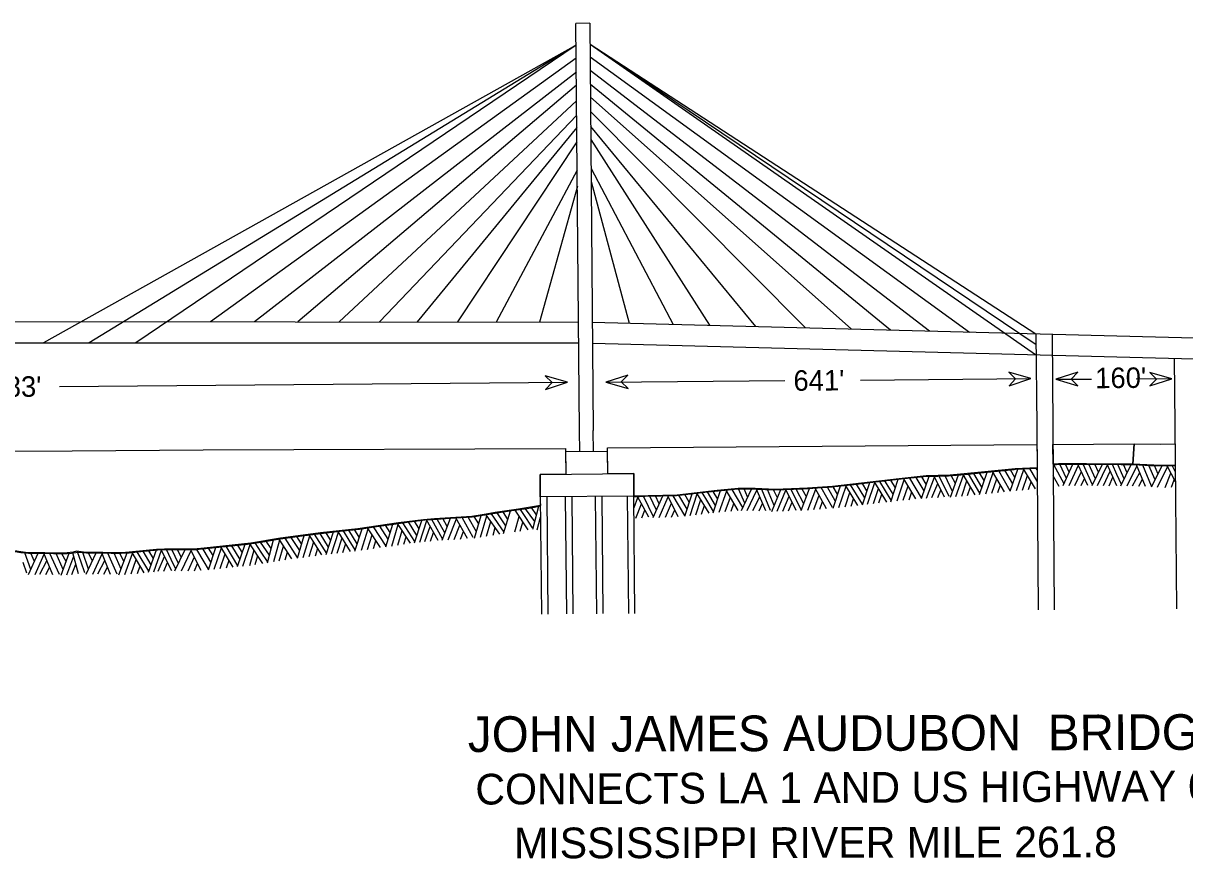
# Model space of a CAD drawing. Extents: x 3250478 to 3288318, y 788638 to 816472.
# Drawn here: x 3261426 to 3266413, y 807945 to 811532 of the extents above; entities that cross this region are included whole.
import ezdxf

# ---------------------------------------------------------------- set-up
doc = ezdxf.new("R2010")
doc.units = 0
doc.layers.add('V-ANNO-SYMB', color=7, linetype='Continuous')

msp = doc.modelspace()

# ---------------------------------------------------------------- linework, layer by layer
at = {"layer": 'V-ANNO-SYMB'}
for p, q in [((3263858.8, 811531.7), (3263798.9, 811531.2)), ((3263858.8, 811531.7), (3263872.4, 809783.7)), ((3263799.7, 811438), (3261513.7, 810158.9)), ((3263799.7, 811438), (3261708.6, 810159)), ((3263799.7, 811438), (3261910, 810159)), ((3263859.5, 811441.7), (3265771.7, 810109.1)), ((3263859.5, 811441.7), (3265774.4, 810153.1)), ((3263859.5, 811441.7), (3265774, 810198.4)), ((3263800.2, 811381.5), (3262230.5, 810249.9)), ((3263859.9, 811388), (3265489, 810205.9)), ((3263800.8, 811322.2), (3262419.6, 810249.8)), ((3265316.7, 810210.3), (3263860.3, 811329)), ((3263860.8, 811270), (3265148.8, 810214.7)), ((3263801.3, 811265.5), (3262604.6, 810249.6)), ((3263801.9, 811198.4), (3262781.9, 810249.5)), ((3263861.2, 811213.6), (3264980.7, 810219.1)), ((3263802.4, 811136.4), (3262954.9, 810249.4)), ((3263861.7, 811152.2), (3264784.4, 810224.2)), ((3263802.9, 811084.6), (3263116.8, 810249.3)), ((3264570.6, 810229.8), (3263862.2, 811088.3)), ((3263803.4, 811022.2), (3263290, 810249.2)), ((3263862.7, 811032.4), (3264372.3, 810234.9)), ((3263804.5, 810900.5), (3263455.9, 810249)), ((3263863.6, 810907.5), (3264217, 810239)), ((3263805.1, 810832.1), (3263642.9, 810248.9)), ((3263864.1, 810852.3), (3264027.3, 810243.9)), ((3261377.1, 810250.5), (3263810.3, 810248.8)), ((3263784.1, 810248.5), (3263784.2, 810248.7)), ((3265774, 810198.4), (3265777.4, 809799.7)), ((3265842.7, 810196.6), (3265846.1, 809800.3)), ((3266398.1, 810182.2), (3267702, 810148.2)), ((3261374.5, 810158.9), (3263811.1, 810159.4)), ((3266367.8, 810093.5), (3266370.2, 809804.7)), ((3266398.9, 810092.7), (3267695.3, 810058.9)), ((3264021.4, 810021.3), (3263927.5, 809991)), ((3263993.5, 809991.6), (3264021.4, 810021.3)), ((3265657.4, 810033.7), (3265686.6, 810005.2)), ((3265752.5, 810005.8), (3265657.4, 810033.7)), ((3265952.9, 810033.2), (3265858.9, 810002.9)), ((3265924.9, 810003.5), (3265952.9, 810033.2)), ((3266262.1, 810032.5), (3266291.2, 810004)), ((3266357.2, 810004.6), (3266262.1, 810032.5)), ((3261581.5, 809972.4), (3263762.2, 809990.1)), ((3263667.1, 810018), (3263696.2, 809989.5)), ((3263762.2, 809990.1), (3263667.1, 810018)), ((3263668.2, 809959.8), (3263762.2, 809990.1)), ((3263696.2, 809989.5), (3263668.2, 809959.8)), ((3263927.5, 809991), (3264695.3, 809997.2)), ((3263927.5, 809991), (3264022.6, 809963.1)), ((3264022.6, 809963.1), (3263993.5, 809991.6)), ((3265020.3, 809999.9), (3265752.5, 810005.8)), ((3265658.6, 809975.5), (3265752.5, 810005.8)), ((3265686.6, 810005.2), (3265658.6, 809975.5)), ((3265858.9, 810002.9), (3266012.8, 810004.1)), ((3265858.9, 810002.9), (3265954, 809975)), ((3265954, 809975), (3265924.9, 810003.5)), ((3266357.2, 810004.6), (3266203.4, 810003.4)), ((3266263.3, 809974.3), (3266357.2, 810004.6)), ((3266291.2, 810004), (3266263.3, 809974.3)), ((3263872, 809783.6), (3263872.7, 809691.9)), ((3265777.4, 809799.7), (3265784, 809012.7)), ((3265846.1, 809800.3), (3265852.7, 809013.2)), ((3266370.2, 809804.7), (3266376.9, 809017.7)), ((3261139.1, 809692.4), (3261636.2, 809696.6)), ((3261636.2, 809696.6), (3262199.2, 809699.8)), ((3263935, 809692.4), (3263754.4, 809690.9)), ((3263754.4, 809690.9), (3263755.1, 809595.8)), ((3263935.8, 809597.3), (3263935, 809692.4)), ((3265895.1, 809554.9), (3265849.9, 809636.2)), ((3265905.2, 809577.8), (3265876.3, 809638.2)), ((3265891.3, 809546.5), (3265932.5, 809639)), ((3265916.7, 809604.8), (3265900.9, 809638.5)), ((3265916.7, 809546.9), (3265956, 809634.8)), ((3265996.5, 809546.9), (3265953.9, 809639)), ((3266017.2, 809550), (3265976.5, 809638.9)), ((3266029.5, 809576.2), (3266001.3, 809638.8)), ((3266015.6, 809546.8), (3266058.9, 809638.6)), ((3266042.6, 809603.6), (3266027, 809638.5)), ((3266038.5, 809546.6), (3266080.3, 809635.2)), ((3266120.9, 809545.8), (3266079.4, 809638.1)), ((3266121.5, 809594.9), (3266102.3, 809637.9)), ((3266152.8, 809575.7), (3266124.8, 809637.6)), ((3266138.5, 809545.6), (3266182.2, 809636.9)), ((3266165.4, 809602), (3266149.9, 809637.3)), ((3266165.9, 809545.2), (3266207.8, 809632.3)), ((3266244.3, 809542.4), (3266205.8, 809636.2)), ((3266269.5, 809543.8), (3266232.3, 809635)), ((3266284.9, 809572), (3266258.8, 809633.6)), ((3266269.7, 809541.4), (3266315, 809631.9)), ((3266297.7, 809598.5), (3266283.4, 809632.9)), ((3266295, 809540.6), (3266338.3, 809626.6)), ((3266372.4, 809563.2), (3266336.4, 809631.4)), ((3266372, 809607.4), (3266358.9, 809632.5)), ((3263644.9, 809594.9), (3264047.2, 809598.2)), ((3263645.7, 809497.9), (3263644.9, 809594.9)), ((3264047.2, 809598.2), (3264048, 809501.2)), ((3265150.6, 809477.6), (3265182.7, 809573.6)), ((3265177.8, 809480.6), (3265208.7, 809572.1)), ((3265258.4, 809489.2), (3265206.3, 809576.1)), ((3265283.1, 809494.4), (3265232.7, 809578.9)), ((3265293.2, 809524.2), (3265259, 809581.7)), ((3265282.3, 809491.7), (3265314.9, 809587.5)), ((3265302.3, 809552.1), (3265283.4, 809584.2)), ((3265303.5, 809492.6), (3265338.5, 809582.8)), ((3265381.1, 809496.3), (3265336.4, 809587.4)), ((3265401.9, 809499.5), (3265358.9, 809587.8)), ((3265416, 809521.4), (3265383.7, 809588.2)), ((3265407.4, 809497), (3265441.2, 809592.7)), ((3265428.5, 809556.3), (3265409.4, 809589.5)), ((3265430.1, 809499.2), (3265462.7, 809591.6)), ((3265512.9, 809507.1), (3265461.6, 809594.3)), ((3265508.1, 809555.9), (3265484.4, 809596.6)), ((3265541.5, 809540.2), (3265506.8, 809598.8)), ((3265530.8, 809508.8), (3265563.9, 809604.4)), ((3265551.2, 809567.9), (3265531.8, 809601.2)), ((3265558.1, 809511.5), (3265589.8, 809602.8)), ((3265584.2, 809514.2), (3265605.7, 809576.3)), ((3265639.3, 809519.8), (3265587.4, 809606.8)), ((3265663.8, 809524.8), (3265613.8, 809609.5)), ((3265674.1, 809554.5), (3265640.2, 809612.2)), ((3265663, 809522.1), (3265695.8, 809617.2)), ((3265683.3, 809581.2), (3265663.9, 809614.5)), ((3265690.2, 809524.9), (3265722, 809616.1)), ((3265716.3, 809527.5), (3265737.8, 809589.6)), ((3265771.4, 809533.1), (3265720.7, 809618.3)), ((3265779.4, 809566.2), (3265747.9, 809619.5)), ((3265779, 809614.2), (3265775.1, 809620.7)), ((3265873.6, 809543), (3265848, 809589.1)), ((3265941.2, 809547.2), (3265968.9, 809606.7)), ((3265968, 809547), (3265982.1, 809577.8)), ((3266063.6, 809546.4), (3266092.6, 809608.6)), ((3266087.6, 809546.2), (3266104.5, 809582.2)), ((3266141.3, 809551.3), (3266121.5, 809594.9)), ((3266189, 809545), (3266219.4, 809603.3)), ((3266214.9, 809543.8), (3266230.9, 809574.7)), ((3266328.4, 809539.1), (3266353, 809599.9)), ((3266355.2, 809540.3), (3266367.7, 809571.8)), ((3264387.8, 809429.5), (3264420.1, 809525.5)), ((3264407.7, 809488.8), (3264388.1, 809522)), ((3264413.6, 809432.7), (3264446.1, 809523.7)), ((3264494.9, 809440.3), (3264443.7, 809527.7)), ((3264515, 809453.1), (3264470.1, 809530.2)), ((3264523.6, 809471.3), (3264496.5, 809532.5)), ((3264509, 809440.4), (3264552.7, 809531.7)), ((3264536, 809498), (3264521.1, 809532.1)), ((3264534.3, 809440.1), (3264576.1, 809526.8)), ((3264613.5, 809437.8), (3264574.1, 809531.4)), ((3264634.4, 809439.9), (3264596.6, 809530.5)), ((3264649.9, 809460.6), (3264621.5, 809529.5)), ((3264639.5, 809436), (3264679, 809529.5)), ((3264664.2, 809493.9), (3264647.1, 809528.2)), ((3264662.3, 809436.7), (3264700.5, 809527)), ((3264745, 809439.4), (3264699.6, 809529.9)), ((3264743.5, 809488.5), (3264722.4, 809530.6)), ((3264777.2, 809467.8), (3264744.9, 809531.3)), ((3264766.5, 809439.6), (3264802.2, 809534.3)), ((3264788.5, 809498.1), (3264770, 809532)), ((3264793.8, 809441.6), (3264828.1, 809531.9)), ((3264875.2, 809447.6), (3264825.8, 809536.1)), ((3264900.1, 809452), (3264852.3, 809538)), ((3264911.1, 809481.4), (3264878.7, 809540)), ((3264902.8, 809449.5), (3264934.6, 809545.5)), ((3264922.3, 809510), (3264903.2, 809542)), ((3264928, 809452.3), (3264958.4, 809543.7)), ((3265009.1, 809461.6), (3264955.9, 809548)), ((3265029.6, 809466.8), (3264978.3, 809550.5)), ((3265038.7, 809494.5), (3265003, 809553.3)), ((3265028.5, 809463.8), (3265060.2, 809560.2)), ((3265048.3, 809523.5), (3265028.5, 809556.3)), ((3265051.1, 809466.4), (3265081.8, 809559.5)), ((3265076.1, 809469.3), (3265097.3, 809534.6)), ((3265133, 809475.6), (3265080.6, 809562.3)), ((3265127.6, 809524.4), (3265103.3, 809564.8)), ((3265161.1, 809509.2), (3265125.7, 809567.3)), ((3265152.5, 809483.5), (3265127.6, 809524.4)), ((3265170.4, 809536.9), (3265150.7, 809570)), ((3265203.4, 809483.4), (3265224.7, 809545.6)), ((3265326.2, 809495.2), (3265352.2, 809555.4)), ((3265352.6, 809495.8), (3265366, 809526.9)), ((3265455.1, 809501.5), (3265477.7, 809566.4)), ((3265479.7, 809503.8), (3265492.6, 809541.5)), ((3265532.5, 809514.7), (3265508.1, 809555.9)), ((3265610, 809516.8), (3265621.3, 809549.8)), ((3265742.2, 809530.1), (3265753.4, 809563.1)), ((3264048, 809501.2), (3263645.7, 809497.9)), ((3263645.7, 809497.9), (3263651, 808994.7)), ((3263679.3, 808994.9), (3263675.1, 809498.2)), ((3263753, 809498.8), (3263758.3, 808995.6)), ((3263786.6, 808995.8), (3263782.4, 809499)), ((3263881.7, 809499.8), (3263887, 808996.6)), ((3263915.3, 808996.9), (3263911.1, 809500.1)), ((3264018.6, 809501), (3264023.9, 808997.8)), ((3264052.2, 808998), (3264048, 809501.2)), ((3264048.4, 809452.2), (3264064.8, 809495.1)), ((3264111.8, 809410.7), (3264062.5, 809499.3)), ((3264131.2, 809412.7), (3264089, 809501.6)), ((3264144.1, 809441.3), (3264115.5, 809501.8)), ((3264130.1, 809410.1), (3264171.7, 809502.4)), ((3264155.8, 809468.3), (3264140, 809502.1)), ((3264156.7, 809410.3), (3264195.2, 809498.5)), ((3264238.3, 809412.1), (3264193.1, 809503)), ((3264266.9, 809418.3), (3264215.7, 809502.1)), ((3264276.1, 809446.1), (3264240.4, 809504.9)), ((3264265.8, 809415.3), (3264297.6, 809511.7)), ((3264285.7, 809475), (3264265.9, 809507.8)), ((3264289.2, 809417.9), (3264319.2, 809511.2)), ((3264314.1, 809420.9), (3264334.9, 809486.4)), ((3264371.3, 809427.8), (3264318, 809513.9)), ((3264365.4, 809476.6), (3264340.7, 809516.7)), ((3264398.4, 809461.1), (3264363.1, 809519.3)), ((3264389.7, 809435.5), (3264364.9, 809476.4)), ((3264439.8, 809435.1), (3264461.8, 809497.1)), ((3264558.2, 809440.1), (3264587.9, 809498.5)), ((3264687.4, 809437.5), (3264713.9, 809500.9)), ((3264711.7, 809438.3), (3264727, 809475.1)), ((3264767.3, 809441.5), (3264743.5, 809488.5)), ((3264820, 809443.5), (3264843.2, 809505)), ((3264845.9, 809445.4), (3264858.1, 809478.1)), ((3264954.1, 809455.3), (3264974.6, 809517.6)), ((3264980.8, 809458.3), (3264991.2, 809490.5)), ((3265099.8, 809472), (3265112.3, 809509.8)), ((3265229.2, 809486.1), (3265240.4, 809519.2)), ((3263471.9, 809338.3), (3263413.9, 809421.6)), ((3263490.3, 809347), (3263436.1, 809425.4)), ((3263498.4, 809374.5), (3263460.5, 809429.6)), ((3263506.7, 809401.5), (3263485.9, 809433.7)), ((3263488.6, 809341.3), (3263517.5, 809438.6)), ((3263593.3, 809356.5), (3263537.8, 809441.2)), ((3263586.1, 809405.1), (3263560.4, 809444.6)), ((3263622.4, 809392.2), (3263582.8, 809447.5)), ((3263629.6, 809420.6), (3263607.5, 809452.1)), ((3263614.2, 809359.9), (3263639.2, 809458)), ((3264056.5, 809406.7), (3264079.9, 809468.2)), ((3264082.4, 809408.6), (3264094.7, 809441.2)), ((3264182.9, 809410.9), (3264209, 809471.1)), ((3264209.8, 809411.5), (3264223, 809442.6)), ((3264338.2, 809423.8), (3264350.2, 809461.8)), ((3264465.6, 809437.5), (3264477.1, 809470.4)), ((3264585, 809439), (3264600.2, 809469.2)), ((3262992.9, 809316.5), (3262956.5, 809372.7)), ((3263000.9, 809344.8), (3262980.8, 809376.2)), ((3262983.2, 809283.7), (3263012.2, 809380.7)), ((3263008.4, 809287.3), (3263036, 809379.5)), ((3263088.9, 809298.8), (3263033.4, 809383.7)), ((3263107.9, 809306.4), (3263055.7, 809386.9)), ((3263116.3, 809331.8), (3263080.2, 809390.4)), ((3263125.7, 809360.8), (3263105.7, 809393.5)), ((3263106.1, 809301), (3263137.4, 809397.5)), ((3263128.8, 809303.7), (3263159.1, 809397)), ((3263207.5, 809311.2), (3263157.9, 809399.5)), ((3263203.6, 809360.1), (3263180.6, 809401.2)), ((3263235.9, 809343.4), (3263203.1, 809403)), ((3263224, 809312.3), (3263260.3, 809406.8)), ((3263246.4, 809370.7), (3263228.2, 809404.7)), ((3263250.5, 809314.2), (3263286.2, 809403.9)), ((3263276.7, 809315.6), (3263300.9, 809376.8)), ((3263333.3, 809319.2), (3263284, 809407.8)), ((3263358.2, 809323.6), (3263310.5, 809409.7)), ((3263371.8, 809348.2), (3263336.9, 809411.6)), ((3263381.5, 809382.6), (3263361.3, 809413.9)), ((3263363.9, 809321.5), (3263392.7, 809418.5)), ((3263389, 809325.1), (3263416.5, 809417.4)), ((3263415, 809328.9), (3263433.5, 809391.9)), ((3263536.2, 809348.1), (3263555.4, 809414.1)), ((3263560.2, 809351.7), (3263571.3, 809389.9)), ((3263612.5, 809365.1), (3263586.1, 809405.1)), ((3263632.7, 809356.9), (3263646.6, 809411.5)), ((3262613.1, 809268), (3262577, 809324.3)), ((3262621.3, 809296.2), (3262601.3, 809327.7)), ((3262603.2, 809235.2), (3262632.7, 809332.1)), ((3262627.7, 809238.6), (3262656.5, 809330.4)), ((3262708.6, 809249.2), (3262653.9, 809334.7)), ((3262728.9, 809254.7), (3262676.3, 809337.6)), ((3262736.6, 809282.1), (3262700.9, 809340.9)), ((3262726.3, 809251.3), (3262758.1, 809347.7)), ((3262746.2, 809311), (3262726.4, 809343.8)), ((3262749, 809253.9), (3262779.7, 809347)), ((3262773.9, 809256.7), (3262795.2, 809322)), ((3262831.4, 809263.4), (3262778.6, 809349.7)), ((3262825.7, 809312.1), (3262801.2, 809352.3)), ((3262859.4, 809297.1), (3262823.6, 809355)), ((3262868.5, 809324.9), (3262848.6, 809357.9)), ((3262849, 809265.4), (3262880.6, 809361.6)), ((3262878.4, 809268.8), (3262906.6, 809361.2)), ((3262959.2, 809280.2), (3262904, 809365.2)), ((3262904.4, 809272.5), (3262923.5, 809335.4)), ((3262984, 809286.4), (3262930.3, 809368.9)), ((3263034.1, 809291), (3263052.8, 809353.9)), ((3263060.6, 809294.8), (3263070.2, 809327.2)), ((3263150, 809306.7), (3263173.6, 809371.2)), ((3263174.2, 809308.6), (3263187.8, 809346)), ((3263226.1, 809318.2), (3263203.1, 809360.1)), ((3263304, 809317.1), (3263316.2, 809349.7)), ((3263443.8, 809333.5), (3263452.3, 809366.2)), ((3262092.4, 809211.9), (3262063.7, 809272)), ((3262077.5, 809180.6), (3262121, 809272)), ((3262105.1, 809237.2), (3262088.8, 809272.2)), ((3262190, 809181.5), (3262144.7, 809272.2)), ((3262203.3, 809218.8), (3262171.2, 809273)), ((3262202.9, 809266.8), (3262197.6, 809275.6)), ((3262220.9, 809185.7), (3262253.5, 809281.5)), ((3262240.9, 809246), (3262222, 809278.2)), ((3262246, 809188.3), (3262277.3, 809279.4)), ((3262327.1, 809196.7), (3262274.8, 809283.7)), ((3262347.6, 809201.7), (3262297.2, 809286)), ((3262357.1, 809229.4), (3262321.9, 809288.6)), ((3262346.6, 809198.8), (3262379.2, 809294.9)), ((3262367, 809258.3), (3262347.5, 809291.3)), ((3262369.3, 809201.2), (3262400.8, 809294)), ((3262455.3, 809212.7), (3262399.6, 809297.2)), ((3262448, 809261.2), (3262422.2, 809300.6)), ((3262483.1, 809247.7), (3262444.5, 809303.8)), ((3262490.8, 809275.9), (3262469.3, 809307.9)), ((3262474.3, 809215.6), (3262501.1, 809313.2)), ((3262501.3, 809220.1), (3262527.1, 809313.2)), ((3262579.5, 809231.9), (3262524.5, 809317)), ((3262524.7, 809224.3), (3262543.9, 809287.2)), ((3262604, 809237.9), (3262550.7, 809320.7)), ((3262653.7, 809242), (3262673.1, 809304.7)), ((3262680.3, 809245.5), (3262690.2, 809277.9)), ((3262798.3, 809259.5), (3262810.5, 809297.4)), ((3262850.9, 809271.4), (3262825.8, 809312.1)), ((3262930.1, 809276.1), (3262940.1, 809309.5)), ((3261458.2, 809186.3), (3261433.4, 809258.1)), ((3261448.2, 809164.6), (3261490.7, 809256.5)), ((3261474.4, 809221.4), (3261458.4, 809256.5)), ((3261477, 809164.6), (3261516.4, 809252.8)), ((3261497.2, 809165.9), (3261527.8, 809224.1)), ((3261552.5, 809163.1), (3261514.3, 809257)), ((3261581.1, 809165.3), (3261540.8, 809255.1)), ((3261597.7, 809186.8), (3261567.4, 809254.8)), ((3261588.3, 809161.6), (3261623.5, 809256.5)), ((3261609.9, 809221.4), (3261591.9, 809254)), ((3261613.6, 809163.6), (3261643.2, 809243)), ((3261662.8, 809168.3), (3261639.3, 809257.8)), ((3261674.6, 809217.3), (3261659.5, 809261.9)), ((3261706.8, 809187.8), (3261681.9, 809259.5)), ((3261696.7, 809166.1), (3261739.2, 809258)), ((3261722.9, 809222.9), (3261707, 809257.9)), ((3261725.5, 809166), (3261764.9, 809254.2)), ((3261745.7, 809167.3), (3261776.4, 809225.5)), ((3261801, 809164.5), (3261762.9, 809258.4)), ((3261829.6, 809166.8), (3261789.4, 809256.6)), ((3261846.2, 809188.2), (3261815.9, 809256.2)), ((3261836.8, 809163), (3261872, 809257.9)), ((3261858.5, 809222.8), (3261840.4, 809255.4)), ((3261862.2, 809165), (3261895.7, 809255.2)), ((3261889.7, 809167.2), (3261911.4, 809229.1)), ((3261944.8, 809172.3), (3261893.3, 809259.8)), ((3261965.3, 809179.2), (3261915.8, 809261.9)), ((3261975, 809206.4), (3261940.5, 809264.5)), ((3261963.6, 809174.6), (3261997.8, 809270.2)), ((3261985, 809233.8), (3261966, 809267.1)), ((3261986.4, 809176.6), (3262019.4, 809268.9)), ((3262006.1, 809178.6), (3262032.7, 809241.9)), ((3262063.7, 809180.4), (3262018.3, 809270.9)), ((3262061.2, 809229.2), (3262041.2, 809271.8)), ((3262080.9, 809187.8), (3262061.2, 809229.2)), ((3262104.9, 809180.3), (3262146.7, 809267.5)), ((3262134.7, 809180), (3262160.7, 809240.4)), ((3262231.8, 809218.1), (3262202.9, 809266.8)), ((3262272.1, 809191), (3262293.2, 809253.2)), ((3262298.8, 809193.8), (3262309.5, 809225.9)), ((3262398.3, 809204.1), (3262417.2, 809270.2)), ((3262422.3, 809207.7), (3262433.3, 809246)), ((3262474.5, 809221.3), (3262448, 809261.2)), ((3262550.4, 809227.9), (3262560.4, 809261.3)), ((3261441.7, 809170.6), (3261426.1, 809215.9)), ((3261523.1, 809164.6), (3261539.3, 809195.5)), ((3261635, 809164.4), (3261651.9, 809209.8)), ((3261690.3, 809172), (3261674.6, 809217.3)), ((3261771.7, 809166), (3261787.8, 809196.9)), ((3261916.4, 809169.7), (3261927.5, 809201.7)), ((3262030.3, 809179.3), (3262045.8, 809216.1)), ((3262160.7, 809180.7), (3262174.3, 809212.8)), ((3262221.3, 809188.3), (3262203.3, 809218.8))]:
    msp.add_line(p, q, dxfattribs=at)
for points in [[(3263814.4, 809783.2), (3263798.9, 811531.2)], [(3263868.8, 810248), (3266230.8, 810186.5), (3266398.1, 810182.2)], [(3263869.5, 810158.6), (3266231.5, 810097.1), (3266398.9, 810092.7)], [(3263815.5, 809691.4), (3263814.7, 809783.2)], [(3265847.5, 809638.2), (3265846.8, 809722.4), (3266195.6, 809725.3), (3266189.7, 809638.4), (3265991.4, 809640.1), (3265889.4, 809640.1), (3265870.9, 809639.9), (3265847.5, 809638.2)], [(3266371.8, 809635), (3266331.3, 809632.9), (3266309.7, 809633.6), (3266189.7, 809638.4), (3266195.6, 809725.3), (3266308, 809725)], [(3266371.8, 809635), (3266331.3, 809632.9), (3266309.7, 809633.6), (3266189.7, 809638.4), (3266195.6, 809725.3), (3266308, 809725)], [(3266308, 809725), (3266371, 809725.7), (3266371.8, 809635)], [(3266308, 809725), (3266371, 809725.7), (3266371.8, 809635)], [(3262199.2, 809699.8), (3263754.2, 809706.6), (3263755.1, 809595.8), (3263644.9, 809594.9), (3263645.7, 809497.9), (3263646, 809476.6), (3263646.1, 809461.3), (3263613, 809455.7), (3263551.8, 809445.1), (3263452.5, 809430.9), (3263404.7, 809422.1), (3263352.2, 809414.5), (3263192, 809404.3), (3263144.8, 809400.2), (3263037.1, 809386.7), (3262862.7, 809360.8), (3262703, 809343.5), (3262530.8, 809320.3), (3262403.3, 809299.9), (3262202.8, 809278.5)], [(3265847.6, 809636), (3265876.6, 809638.2), (3265937.8, 809639.1), (3266011.1, 809638.7), (3266084.4, 809638.1), (3266139, 809637.5), (3266193.6, 809636.8), (3266263.6, 809633.5), (3266333.6, 809631.3), (3266371.8, 809633.1)], [(3264048, 809498.2), (3264095.7, 809501.6), (3264163.5, 809502.3), (3264231.2, 809503.9), (3264291.8, 809510.8), (3264352.4, 809518.1), (3264423.3, 809525.8), (3264494.4, 809532.5), (3264572.7, 809531.4), (3264651, 809528.3), (3264774.4, 809532.3), (3264897.7, 809541.4), (3264991.4, 809552), (3265084.9, 809562.7), (3265195.6, 809575), (3265306.3, 809586.6), (3265352.5, 809587.7), (3265398.8, 809588.5), (3265468.2, 809595), (3265537.6, 809601.8), (3265609.2, 809609.1), (3265680.7, 809616.2), (3265686.2, 809616.7), (3265778.9, 809620.9)], [(3262521.2, 809316.6), (3262612.5, 809329.3), (3262703.9, 809341.2), (3262786.5, 809350.6), (3262869.1, 809360.3), (3262942.8, 809370.7), (3263016.6, 809381.3), (3263084.2, 809390.9), (3263152, 809399), (3263203.8, 809403.1), (3263255.5, 809406.5), (3263304.6, 809409.3), (3263353.6, 809412.8), (3263415.9, 809421.9), (3263478, 809432.6), (3263534.1, 809440.7), (3263590.2, 809448.9), (3263621.1, 809454.7), (3263646.1, 809459.4)], [(3262202.8, 809278.5), (3262172.6, 809275.3), (3262032.8, 809273.3), (3261998, 809272.1), (3261850.6, 809258.3), (3261767.6, 809260.1), (3261694.5, 809259.5), (3261654.7, 809264.6), (3261639.8, 809260.4)], [(3261639.9, 809257.9), (3261664, 809261.4), (3261697.2, 809257.9), (3261729.7, 809258), (3261762.3, 809258.5), (3261804.2, 809256.4), (3261846, 809255.9), (3261881.3, 809258.6), (3261916.5, 809262), (3261960, 809266.5), (3262003.5, 809270.4), (3262050.9, 809271.9), (3262098.3, 809272.3), (3262134.1, 809271.9), (3262169.9, 809272.9), (3262202.8, 809276.2)], [(3262202.8, 809276.2), (3262210.7, 809277), (3262251.4, 809281.3), (3262320.3, 809288.4), (3262389.1, 809295.6), (3262455.2, 809305.6), (3262521.2, 809316.6)], [(3261392.1, 809264.2), (3261415.5, 809260), (3261448.7, 809256.5), (3261481.2, 809256.5), (3261513.7, 809257.1), (3261555.6, 809255), (3261597.5, 809254.4), (3261632.8, 809257.2), (3261639.9, 809257.9)], [(3261639.8, 809260.4), (3261602.1, 809256.9), (3261519, 809258.7), (3261445.9, 809258.1), (3261406.2, 809263.2), (3261393, 809265.9)]]:
    msp.add_lwpolyline(points, dxfattribs=at)
msp.add_lwpolyline([(3263934.9, 809708.7), (3265778.1, 809723.2), (3265778.5, 809663.8), (3265778.9, 809623.1), (3265683.9, 809618.6), (3265554.6, 809605.8), (3265404.8, 809591.1), (3265301.9, 809588.5), (3265187.2, 809575.8), (3264899.8, 809543.2), (3264793, 809535.6), (3264654.2, 809530.2), (3264568, 809533.7), (3264495.6, 809534.3), (3264405.4, 809526), (3264233.3, 809506.1), (3264048, 809501.2), (3264047.2, 809598.2), (3263936, 809597.3), (3263935.8, 809597.3)], close=True, dxfattribs=at)

# ---------------------------------------------------------------- texts
for s, height, rotation, p in [("641'", 87.98, 0.4666, (3264733, 809953.6)), ("160'", 87.98, 0.4666, (3266028.5, 809964.6)), ("1583'", 87.98, 0.4666, (3261220.4, 809926.1)), ('JOHN JAMES AUDUBON  BRIDGE', 153.014, 0.1736, (3263335.2, 808402.7)), ('CONNECTS LA 1 AND US HIGHWAY 61', 131.91, 0.2641, (3263367.5, 808177.2)), ('MISSISSIPPI RIVER MILE 261.8', 131.91, 0.1133, (3263533.4, 807946))]:
    msp.add_text(s, height=height, rotation=rotation, dxfattribs=at).set_placement(p)

doc.saveas('drawing.dxf')
